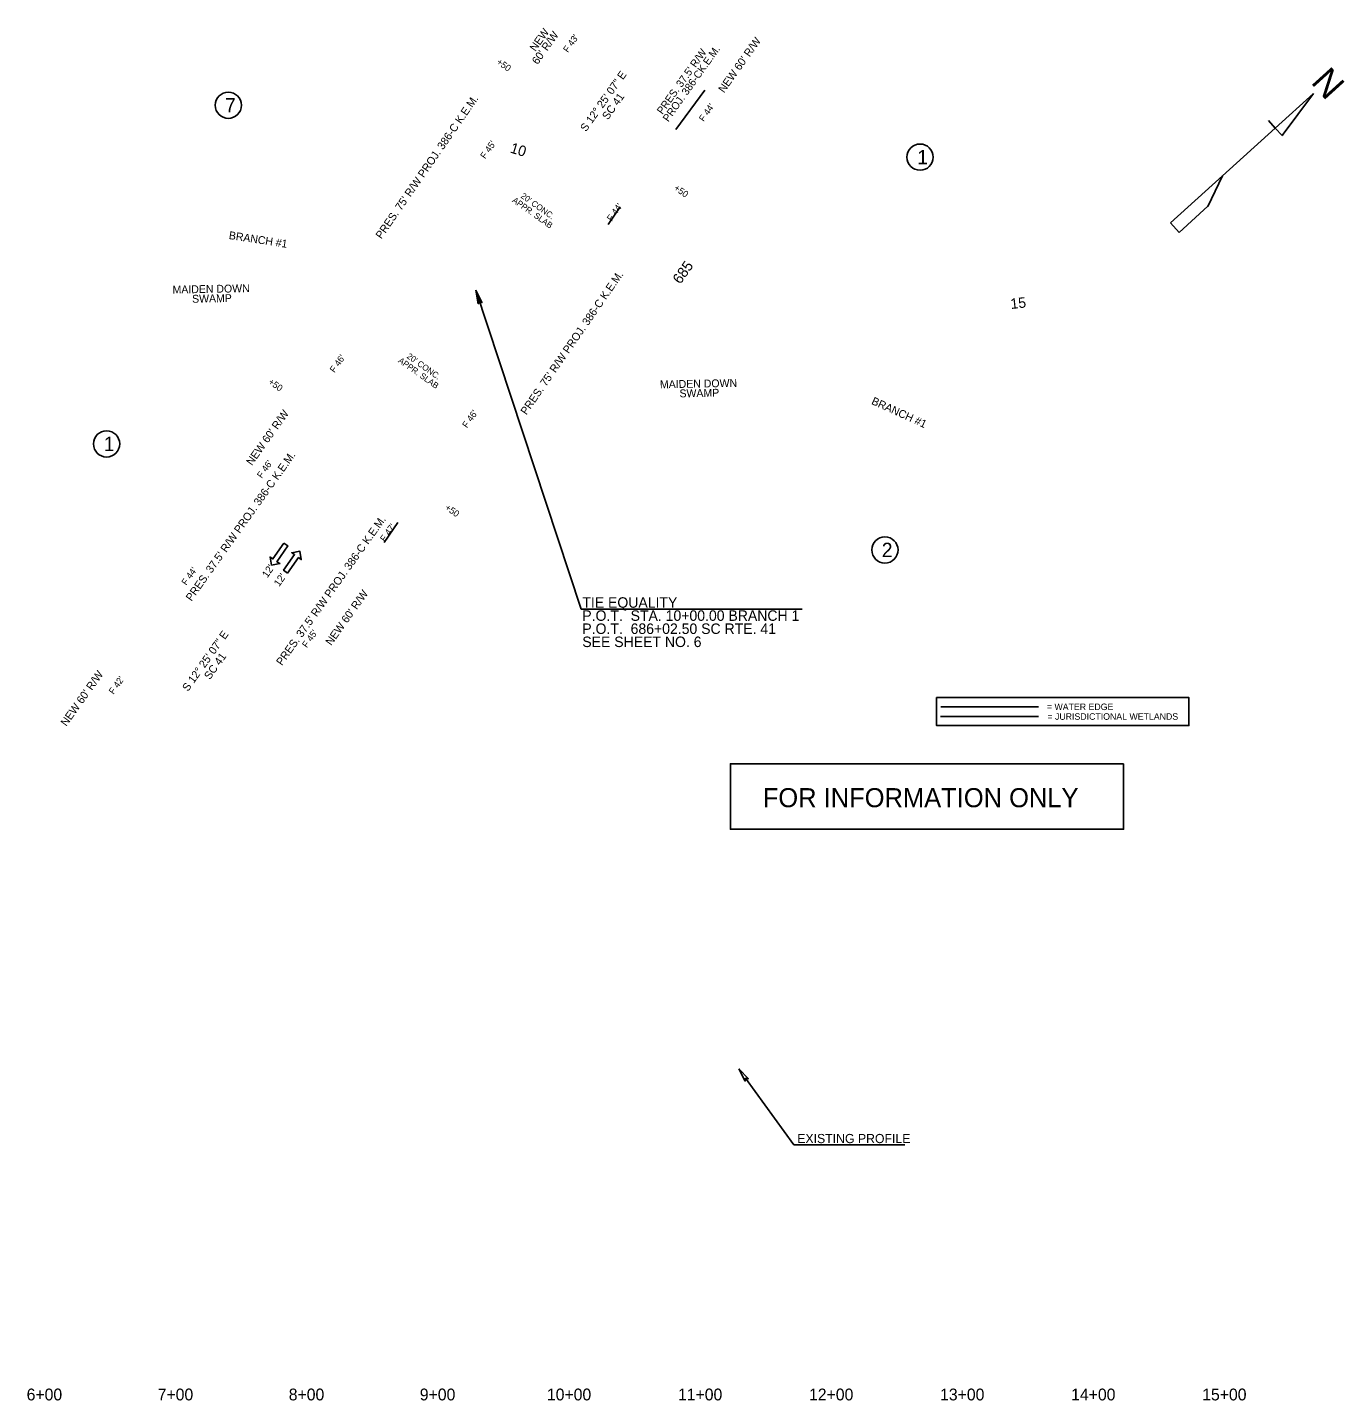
# Model space of a CAD drawing. Extents: x 2522404 to 2525275, y 885432 to 893540.
# Drawn here: x 2523476 to 2524481, y 892426 to 893474 of the extents above; entities that cross this region are included whole.
import ezdxf

# ---------------------------------------------------------------- set-up
doc = ezdxf.new("R2010")
doc.units = 0
for name, color, linetype in [('Default', 7, 'Continuous'), ('GN_Clip', 7, 'Continuous'), ('RD_DDB_Profile_EX', 7, 'Continuous'), ('RD_DDB_Profile_Lbl', 7, 'Continuous'), ('RD_DDB_StaTX', 7, 'Continuous'), ('RD_EV_JW', 7, 'Continuous'), ('RD_EX_H2O', 7, 'Continuous'), ('RD_EX_Misc', 7, 'Continuous'), ('RD_EX_VEG', 7, 'Continuous'), ('RD_HC_Cl', 7, 'Continuous'), ('RD_PD_Final_LnLine', 7, 'Continuous'), ('RD_PD_RW_TX', 7, 'Continuous'), ('RD_SHT_IplotShp', 7, 'Continuous'), ('RD_Sketch1', 7, 'Continuous'), ('RD_Sketch8', 7, 'Continuous'), ('RD_SMD_Locator', 7, 'Continuous'), ('RD_TX_Profile', 7, 'Continuous')]:
    doc.layers.add(name, color=color, linetype=linetype)

# ---------------------------------------------------------------- blocks, each defined once
blk = doc.blocks.new('AH4_')
at = {"layer": 'Default'}
blk.add_lwpolyline([(0, 0), (-10.4, 1.5), (-8.8, 0), (-10.4, -1.5)], close=True, dxfattribs=at)

msp = doc.modelspace()

# ---------------------------------------------------------------- linework, layer by layer
at = {"layer": 'Default'}
for points in [[(2523671.8, 893080.2), (2523674.9, 893078.1), (2523666.6, 893066), (2523668.8, 893064.6), (2523662.5, 893063.4), (2523661.4, 893069.6), (2523663.5, 893068.2)], [(2523674.7, 893057.3), (2523671.6, 893059.5), (2523680, 893071.4), (2523677.9, 893072.9), (2523684.1, 893074), (2523685.2, 893067.7), (2523683.1, 893069.2)], [(2524169.9, 892962.4), (2524362.4, 892962.4), (2524362.4, 892941), (2524169.9, 892941)]]:
    msp.add_lwpolyline(points, close=True, dxfattribs=at)
at = {"layer": 'RD_DDB_StaTX'}
for p in [(2524024.2, 892671.9), (2524145.6, 892621.2)]:
    msp.add_line(p, (2524060.9, 892621.2), dxfattribs=at)
at = {"layer": 'RD_EV_JW'}
msp.add_line((2524172.9, 892947.9), (2524247.8, 892947.9), dxfattribs=at)
at = {"layer": 'RD_EX_H2O'}
msp.add_line((2524247.6, 892955.3), (2524173.2, 892955.3), dxfattribs=at)
at = {"layer": 'RD_EX_Misc'}
for centre in [(2523629.5, 893414.3), (2524157.3, 893374.7), (2523536.6, 893155.9), (2524130.5, 893075)]:
    msp.add_circle(centre, 10, dxfattribs=at)
at = {"layer": 'RD_EX_VEG'}
for points in [[(2523971, 893395.7), (2523993.1, 893425.7)], [(2523919.4, 893323.2), (2523928.5, 893336.8)], [(2523748.4, 893080.7), (2523758.9, 893095.9)]]:
    msp.add_lwpolyline(points, dxfattribs=at)
at = {"layer": 'RD_PD_RW_TX'}
for p, q in [((2523818.4, 893273.2), (2523898.6, 893029.8)), ((2523898.6, 893029.8), (2524067.3, 893029.8))]:
    msp.add_line(p, q, dxfattribs=at)
at = {"layer": 'RD_Sketch8'}
for p, q in [((2524457.4, 893423.2), (2524428.4, 893396.9)), ((2524433.6, 893391.1), (2524457.4, 893423.2)), ((2524457.4, 893423.2), (2524457.4, 893423.2)), ((2524423.1, 893402.7), (2524428.4, 893396.9)), ((2524388, 893360.4), (2524428.4, 893396.9)), ((2524428.4, 893396.9), (2524433.6, 893391.1)), ((2524433.6, 893391.1), (2524434, 893391.4)), ((2524388, 893360.4), (2524348.4, 893324.5)), ((2524376.8, 893337), (2524388, 893360.4)), ((2524355, 893317.3), (2524377, 893337.2)), ((2524377, 893337.2), (2524376.8, 893337)), ((2524348.4, 893324.5), (2524355, 893317.3))]:
    msp.add_line(p, q, dxfattribs=at)
at = {"layer": 'RD_TX_Profile'}
msp.add_lwpolyline([(2524312.6, 892911.9), (2524012.6, 892911.9), (2524012.6, 892861.9), (2524312.6, 892861.9)], close=True, dxfattribs=at)

# ---------------------------------------------------------------- block references
at = {"layer": 'RD_PD_Final_LnLine'}
for p, rotation in [((2523818.4, 893273.2), 107.96376358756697), ((2524019, 892679), 126.10500968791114)]:
    msp.add_blockref('AH4_', p, dxfattribs=dict(at, rotation=rotation))

# ---------------------------------------------------------------- texts
at = {"layer": 'Default'}
msp.add_text('FOR INFORMATION ONLY', height=14.542, dxfattribs=at).set_placement((2524037.3, 892878.7))
at = {"layer": 'GN_Clip'}
for s, p in [('6+00', (2523475.6, 892426.1)), ('7+00', (2523575.6, 892426.1)), ('8+00', (2523675.6, 892426.1)), ('9+00', (2523775.6, 892426.1)), ('10+00', (2523872.6, 892426.1)), ('11+00', (2523972.6, 892426.1)), ('12+00', (2524072.6, 892426.1)), ('13+00', (2524172.6, 892426.1)), ('14+00', (2524272.6, 892426.1)), ('15+00', (2524372.6, 892426.1))]:
    msp.add_text(s, height=9, dxfattribs=at).set_placement(p)
at = {"layer": 'RD_DDB_Profile_EX'}
for s, height, rotation, p in [('10', 8, 343.269, (2523844, 893378.3)), ('APPR. SLAB', 4.6, 324.5691, (2523845.7, 893340.8)), ("20' CONC.", 4.6, 324.5691, (2523852.2, 893344.1)), ('685', 8, 54.5691, (2523974.4, 893277.3)), ('15', 8, 5.9376, (2524226.7, 893258.8)), ("20' CONC.", 4.6, 324.5691, (2523765.2, 893221.8)), ('APPR. SLAB', 4.6, 324.5691, (2523758.7, 893218.5))]:
    msp.add_text(s, height=height, rotation=rotation, dxfattribs=at).set_placement(p)
at = {"layer": 'RD_DDB_Profile_Lbl'}
for s, p in [('7', (2523627, 893408.8)), ('1', (2524155.2, 893369.2)), ('1', (2523534.4, 893150.4)), ('2', (2524128.1, 893069.5))]:
    msp.add_text(s, height=11, dxfattribs=at).set_placement(p)
at = {"layer": 'RD_DDB_StaTX'}
for p in [(2523659.3, 893053.3), (2523668.3, 893046.6)]:
    msp.add_text("12'", height=5.6, rotation=55.1491, dxfattribs=at).set_placement(p)
msp.add_text('EXISTING PROFILE', height=7, dxfattribs=at).set_placement((2524063.6, 892622.4))
at = {"layer": 'RD_EV_JW'}
for s, p in [('= WATER EDGE', (2524254.1, 892952.8)), ('= JURISDICTIONAL WETLANDS', (2524254.5, 892945.4))]:
    msp.add_text(s, height=5, dxfattribs=at).set_placement(p)
at = {"layer": 'RD_HC_Cl'}
for s, height, rotation, p in [('S 12%%d 25\' 07" E', 6, 54.5691, (2523902.4, 893393.7)), ('SC 41', 6, 54.5691, (2523919.1, 893402.7)), ('BRANCH #1', 6, 351.2538, (2523629.6, 893312.3)), ('MAIDEN DOWN', 6, 1.0995, (2523587, 893270.6)), ('SWAMP', 6, 1.0995, (2523601.9, 893263.6)), ('MAIDEN DOWN', 6, 1.0995, (2523958.9, 893198.3)), ('SWAMP', 6, 1.0995, (2523973.8, 893191.4)), ('BRANCH #1', 6, 335.5259, (2524119.7, 893186.5)), ('TIE EQUALITY', 8, 360, (2523899.6, 893030.9)), ('P.O.T.  STA. 10+00.00 BRANCH 1', 8, 360, (2523899.6, 893020.9)), ('P.O.T.  686+02.50 SC RTE. 41', 8, 360, (2523899.6, 893010.9)), ('S 12%%d 25\' 07" E', 6, 54.5691, (2523598.7, 892966.6)), ('SEE SHEET NO. 6', 8, 360, (2523899.6, 893000.9)), ('SC 41', 6, 54.5691, (2523615.4, 892975.6))]:
    msp.add_text(s, height=height, rotation=rotation, dxfattribs=at).set_placement(p)
at = {"layer": 'RD_SHT_IplotShp'}
for s, height, rotation, p in [("PRES. 37.5' R/W ", 5.75, 54.5691, (2523960.7, 893406.9)), ('PROJ. 386-CK.E.M.', 5.75, 54.5691, (2523965.2, 893401.2)), ('+50', 5, 324.5691, (2523833.7, 893446.3)), ("PRES. 75' R/W PROJ. 386-C K.E.M.", 6, 55.3777, (2523746.3, 893311.8)), ('+50', 5, 324.5691, (2523969, 893350.1)), ("PRES. 75' R/W PROJ. 386-C K.E.M.", 6, 55.3777, (2523856.9, 893177.6)), ('+50', 5, 324.5691, (2523659.5, 893202.2)), ("PRES. 37.5' R/W PROJ. 386-C K.E.M.", 6, 54.5691, (2523601.4, 893035.4)), ('+50', 5, 324.5691, (2523794.3, 893106.3)), ("PRES. 37.5' R/W PROJ. 386-C K.E.M.", 6, 54.5691, (2523670.4, 892986.3))]:
    msp.add_text(s, height=height, rotation=rotation, dxfattribs=at).set_placement(p)
at = {"layer": 'RD_Sketch1'}
for s, p in [('NEW', (2523863.8, 893454.9)), ("60' R/W", (2523865.5, 893444.9)), ("NEW 60' R/W", (2524007.7, 893423.3)), ("NEW 60' R/W", (2523647.5, 893139)), ("NEW 60' R/W", (2523708, 893001.6)), ("NEW 60' R/W", (2523505.9, 892940))]:
    msp.add_text(s, height=6, rotation=54.5691, dxfattribs=at).set_placement(p)
at = {"layer": 'RD_Sketch8'}
msp.add_text('N', height=20, rotation=312.1506, dxfattribs=at).set_placement((2524454.9, 893431.5))
at = {"layer": 'RD_SMD_Locator'}
for s, p in [("F 43'", (2523888.6, 893454.1)), ("F 44'", (2523992.2, 893401.4)), ("F 45'", (2523825.4, 893373)), ("F 44'", (2523922, 893325.3)), ("F 46'", (2523710.5, 893209.8)), ("F 46'", (2523811.6, 893167.6)), ("F 46'", (2523655, 893129.3)), ("F 47'", (2523748.9, 893080.8)), ("F 44'", (2523597.4, 893047.6)), ("F 45'", (2523689.4, 892999.9)), ("F 42'", (2523541.9, 892964.4))]:
    msp.add_text(s, height=5, rotation=54.5691, dxfattribs=at).set_placement(p)

doc.saveas('drawing.dxf')
